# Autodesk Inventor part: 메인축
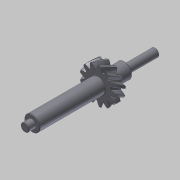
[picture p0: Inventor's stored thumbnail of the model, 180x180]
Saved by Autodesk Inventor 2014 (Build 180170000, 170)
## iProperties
Created: 2018-07
Part Number: 메인축
Material: 강철
Document SubType Name: Modeling
Designer: mduedu
Categories: <?xml version="1.0" encoding="UTF-16"?> <MemberInstance><Categories><FamilyTemplate><FamilyTemplateParameter ValueType="xs:double" Id="1" ObjectReferenceKey="da
Density: 7.85 g/cm^3
Mass: 182.309 g
Surface Area: 79.8926 cm^2
Volume: 23.2241 cm^3
Appearance: 강철
CustomPartVersion: 1
Author: mduedu
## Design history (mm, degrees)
sketch "Sketch1"
  geometry: C1 r 17.232 at (0, 0)
  constraints: 1 centre point
  dimensions: "d0" = 34.46497 diameter of C1 (= da_da)
extrude "Extrusion1" new body sketch "Sketch1" distance "d1" = 10 (= da_b); taper "d2" = 0 deg
workplane "Work Plane2"
sketch "Sketch2"
  geometry: C1 r 17.232 at (0, 0) reference; C2 r 15.087 at (0, 0)
  constraints: 1 centre point, 1 coincident
  dimensions: "d3" = 30.17368 diameter of C2 (= da_dw)
feature "피치 지름" sketch "Sketch2" dims "d4" = 10, "d5" = 0
workplane "Work Plane8"
workplane "Work Plane9"
feature "스퍼 기어" dims "da_b" = 10, "da_d" = 30.02221, "da_aw" = 44.1, "da_da" = 34.46497, "da_df" = 25.47121, "da_dw" = 30.17368, angle "da_beta" = 30 deg, "da_lefttooth" = 0, "da_righttooth" = 10
sketch "스케치3"
  geometry: C1 r 7.5 at (0, 0); 1 further point
  constraints: 1 centre point, 1 coincident
  dimensions: "d49" = 15 diameter of C1
extrude "돌출2" join sketch "스케치3" distance "d50" = 64; taper "d51" = 0 deg
sketch "스케치4"
  geometry: C1 r 4 at (0, 0); 1 further point
  constraints: 1 centre point, 1 coincident
  dimensions: "d52" = 8 diameter of C1
extrude "돌출3" join sketch "스케치4" distance "d53" = 7; taper "d54" = 0 deg
sketch "스케치5"
  geometry: C1 r 7.5 at (0, 0) reference; C2 r 7.5 at (0, 0) reference; 1 further point
extrude "돌출4" join sketch "스케치5" distance "d55" = 16; taper "d56" = 0 deg
sketch "스케치6"
  geometry: C1 r 4 at (0, 0); 1 further point
  constraints: 1 centre point, 1 coincident
  dimensions: "d57" = 8 diameter of C1
extrude "돌출5" join sketch "스케치6" distance "d58" = 30; taper "d59" = 0 deg
chamfer "모따기1" distance "d60" = 0.5; stored, may be unused: second distance "d61" = 2, angle "d62" = 45 deg
fillet "모깎기1" dims "d63" = 0.5
body "Solid1"
body "Srf1"
node "투영된 루프1"
other parameters: "d16" = 44.1 (= da_aw), "d17" = 0, "d34" = 2.41661 (computed from da_z), "d39" = 0, "d41" = 0, "d43" = 44.1 (= da_aw), "d46" = 44.1 (= da_aw), "d47" = 0, "d48" = 0
